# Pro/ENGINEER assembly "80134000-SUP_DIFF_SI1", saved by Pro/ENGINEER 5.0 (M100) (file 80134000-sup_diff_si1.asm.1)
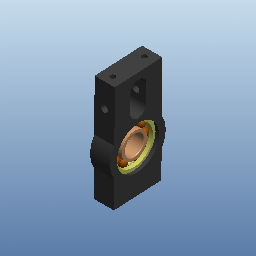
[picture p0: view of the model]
Units: millimeter Newton Second (mmNs); MM, TONNE, HOURS

Other components: 80134000-PALIER_DIFF_ETROIT_SI1, RLT-6001_D12-SERIE10

Other named items: 80134000-PALIER_DIFF_ETROIT_01, A-DROITE, A-DESSUS, A-FACE, A-R0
